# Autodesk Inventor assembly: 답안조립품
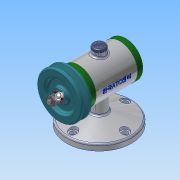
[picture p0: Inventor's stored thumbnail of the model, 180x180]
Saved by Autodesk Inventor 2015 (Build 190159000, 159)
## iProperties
Created: 2018-12
Part Number: 답안조립품
Document SubType Name: Assembly
Designer: user
Author: user
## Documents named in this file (15)
- C:\Users\user\Desktop\481207v1069\답안조립품.iam
- C:\Users\user\Desktop\481207v1069\본체.ipt
- C:\Users\user\Desktop\481207v1069\앞커버.ipt
- C:\Users\user\Desktop\481207v1069\뒤커버.ipt
- C:\Users\user\Desktop\481207v1069\오일 실 15 25 7.ipt
- C:\Users\user\Desktop\481207v1069\축.ipt
- C:\Users\user\Desktop\481207v1069\키 3 x 3 x 12.ipt
- C:\Users\user\Desktop\481207v1069\베어링 15 x 32 x 9.ipt
- C:\Users\user\Desktop\481207v1069\V벨트풀리.ipt
- C:\Users\user\Desktop\481207v1069\와셔 8x17.ipt
- C:\Users\user\Desktop\481207v1069\스프링와셔 8.ipt
- C:\Users\user\Desktop\481207v1069\고무캡.ipt
- C:\Users\user\Desktop\481207v1069\너트 M8.ipt
- 너트 M8.ipt
- C:\Users\user\Desktop\481207v1069\볼트 M4 x 12.ipt
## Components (2 placed, 2 different names)
1. V벨트풀리:1
2. 고무캡:1
